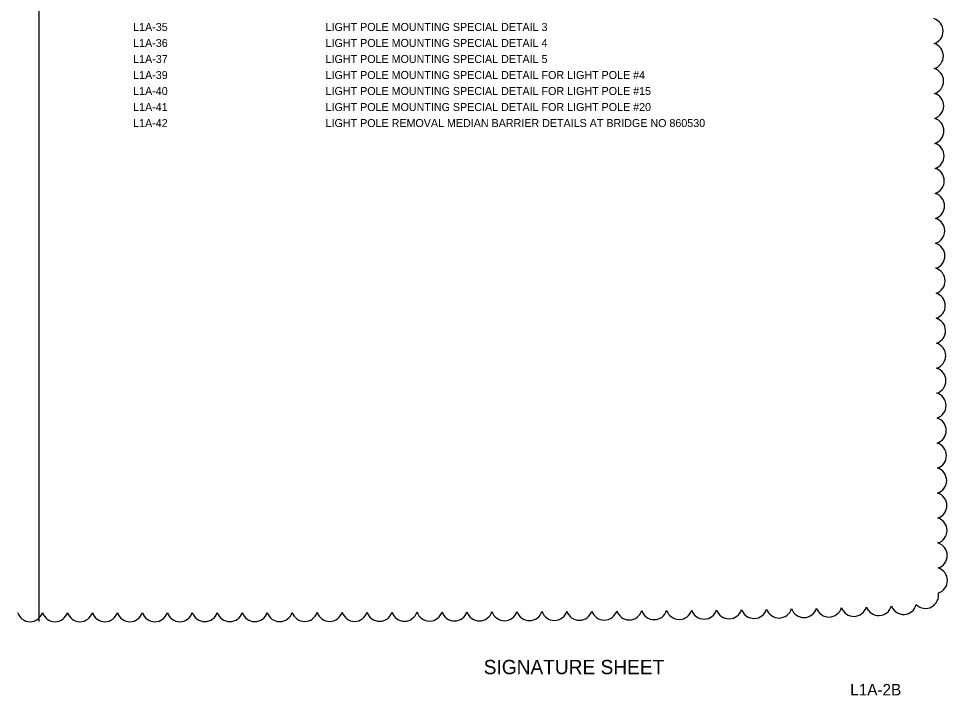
# Model space of a CAD drawing. Extents: x -811.2 to -795.1, y -2238.2 to -2204.
# Drawn here: x -803.27 to -795.14, y -2238.18 to -2232.26 of the extents above; entities that cross this region are included whole.
import ezdxf

# ---------------------------------------------------------------- set-up
doc = ezdxf.new("R2010")
doc.units = 0
for name, color, linetype in [('Cloud_dp', 7, 'Continuous'), ('PlotBorder_dp', 7, 'Continuous'), ('SheetLines_dp', 7, 'Continuous'), ('TextMisc', 7, 'Continuous'), ('TextNotes', 7, 'Continuous')]:
    doc.layers.add(name, color=color, linetype=linetype)

msp = doc.modelspace()

# ---------------------------------------------------------------- linework, layer by layer
at = {"layer": 'Cloud_dp'}
for centre, radius, start, end in [((-795.2963, -2232.3679), 0.1145, 287.95289, 72.95289), ((-795.2945, -2232.5862), 0.1145, 287.95287, 72.95287), ((-795.2928, -2232.8045), 0.1145, 287.95266, 72.95266), ((-795.2911, -2233.0228), 0.1145, 287.95242, 72.95242), ((-795.2894, -2233.2411), 0.1145, 287.95215, 72.95215), ((-795.2876, -2233.4594), 0.1145, 287.95186, 72.95186), ((-795.2859, -2233.6778), 0.1145, 287.95154, 72.95154), ((-795.2842, -2233.8961), 0.1145, 287.9512, 72.9512), ((-795.2825, -2234.1144), 0.1145, 287.95082, 72.95082), ((-795.2808, -2234.3327), 0.1145, 287.9504, 72.9504), ((-795.279, -2234.551), 0.1145, 287.94993, 72.94993), ((-795.2773, -2234.7693), 0.1145, 287.9494, 72.9494), ((-795.2756, -2234.9877), 0.1145, 287.94881, 72.94881), ((-795.2739, -2235.206), 0.1145, 287.94812, 72.94812), ((-795.2722, -2235.4243), 0.1145, 287.94732, 72.94732), ((-795.2705, -2235.6426), 0.1145, 287.94637, 72.94637), ((-795.2688, -2235.8609), 0.1145, 287.94522, 72.94522), ((-795.2671, -2236.0792), 0.1145, 287.94379, 72.94379), ((-795.2654, -2236.2976), 0.1145, 287.94193, 72.94193), ((-795.2637, -2236.5159), 0.1145, 287.93937, 72.93937), ((-795.2621, -2236.7342), 0.1145, 287.93555, 72.93555), ((-795.2604, -2236.9525), 0.1145, 287.92882, 72.92882), ((-795.2588, -2237.1708), 0.1145, 287.91061, 72.91061), ((-795.3362, -2237.3006), 0.1144, 225.47981, 10.47981), ((-797.7084, -2237.3989), 0.1145, 198.05689, 343.05689), ((-797.4901, -2237.3967), 0.1145, 198.11741, 343.11741), ((-797.2718, -2237.3942), 0.1145, 198.18739, 343.18739), ((-797.0536, -2237.3914), 0.1145, 198.26957, 343.26957), ((-796.8353, -2237.3883), 0.1145, 198.36798, 343.36798), ((-796.6171, -2237.3848), 0.1145, 198.48877, 343.48877), ((-796.3989, -2237.3807), 0.1145, 198.642, 343.642), ((-796.1808, -2237.376), 0.1145, 198.84545, 343.84545), ((-795.9627, -2237.3703), 0.1145, 199.13452, 344.13452), ((-795.7448, -2237.3632), 0.1145, 199.59428, 344.59428), ((-795.5272, -2237.3535), 0.1145, 200.51668, 345.51668), ((-803.1661, -2237.4174), 0.1145, 197.49598, 342.49598), ((-802.9478, -2237.4174), 0.1145, 197.50115, 342.50115), ((-802.7294, -2237.4174), 0.1145, 197.51106, 342.51106), ((-802.5111, -2237.4173), 0.1145, 197.52205, 342.52205), ((-802.2928, -2237.4172), 0.1145, 197.53355, 342.53355), ((-802.0745, -2237.4171), 0.1145, 197.54559, 342.54559), ((-801.8562, -2237.4169), 0.1145, 197.55822, 342.55822), ((-801.6379, -2237.4166), 0.1145, 197.57149, 342.57149), ((-801.4195, -2237.4163), 0.1145, 197.58546, 342.58546), ((-801.2012, -2237.416), 0.1145, 197.60019, 342.60019), ((-800.9829, -2237.4156), 0.1145, 197.61574, 342.61574), ((-800.7646, -2237.4151), 0.1145, 197.63221, 342.63221), ((-800.5463, -2237.4146), 0.1145, 197.64968, 342.64968), ((-800.328, -2237.414), 0.1145, 197.66826, 342.66826), ((-800.1097, -2237.4133), 0.1145, 197.68807, 342.68807), ((-799.8914, -2237.4125), 0.1145, 197.70926, 342.70926), ((-799.673, -2237.4117), 0.1145, 197.73198, 342.73198), ((-799.4547, -2237.4107), 0.1145, 197.75645, 342.75645), ((-799.2364, -2237.4097), 0.1145, 197.78289, 342.78289), ((-799.0181, -2237.4086), 0.1145, 197.81157, 342.81157), ((-798.7998, -2237.4073), 0.1145, 197.84285, 342.84285), ((-798.5815, -2237.406), 0.1145, 197.87713, 342.87713), ((-798.3632, -2237.4045), 0.1145, 197.91494, 342.91494), ((-798.1449, -2237.4028), 0.1145, 197.9569, 342.9569), ((-797.9267, -2237.401), 0.1145, 198.00386, 343.00386)]:
    msp.add_arc(centre, radius, start, end, dxfattribs=at)
at = {"layer": 'TextNotes'}
msp.add_line((-803.0858, -2237.5311), (-803.0858, -2227.9311), dxfattribs=at)

# ---------------------------------------------------------------- texts
at = {"layer": 'PlotBorder_dp'}
msp.add_text('       SIGNATURE SHEET         ', height=0.125, dxfattribs=at).set_placement((-799.5241, -2237.9903))
at = {"layer": 'SheetLines_dp'}
msp.add_text('L1A-2B', height=0.1, dxfattribs=at).set_placement((-795.9942, -2238.176))
at = {"layer": 'TextMisc'}
for s, p in [('L1A-35', (-802.2643, -2232.3667)), ('LIGHT POLE MOUNTING SPECIAL DETAIL 3', (-800.5815, -2232.3667)), ('L1A-36', (-802.2643, -2232.5067)), ('LIGHT POLE MOUNTING SPECIAL DETAIL 4', (-800.5815, -2232.5067)), ('L1A-37', (-802.2643, -2232.6467)), ('LIGHT POLE MOUNTING SPECIAL DETAIL 5', (-800.5815, -2232.6467)), ('L1A-39', (-802.2643, -2232.7867)), ('LIGHT POLE MOUNTING SPECIAL DETAIL FOR LIGHT POLE #4', (-800.5815, -2232.7867)), ('L1A-40', (-802.2643, -2232.9267)), ('LIGHT POLE MOUNTING SPECIAL DETAIL FOR LIGHT POLE #15', (-800.5815, -2232.9267)), ('L1A-41', (-802.2643, -2233.0667)), ('LIGHT POLE MOUNTING SPECIAL DETAIL FOR LIGHT POLE #20', (-800.5815, -2233.0667)), ('L1A-42', (-802.2643, -2233.2067)), ('LIGHT POLE REMOVAL MEDIAN BARRIER DETAILS AT BRIDGE NO 860530', (-800.5815, -2233.2067))]:
    msp.add_text(s, height=0.07, dxfattribs=at).set_placement(p)

doc.saveas('drawing.dxf')
